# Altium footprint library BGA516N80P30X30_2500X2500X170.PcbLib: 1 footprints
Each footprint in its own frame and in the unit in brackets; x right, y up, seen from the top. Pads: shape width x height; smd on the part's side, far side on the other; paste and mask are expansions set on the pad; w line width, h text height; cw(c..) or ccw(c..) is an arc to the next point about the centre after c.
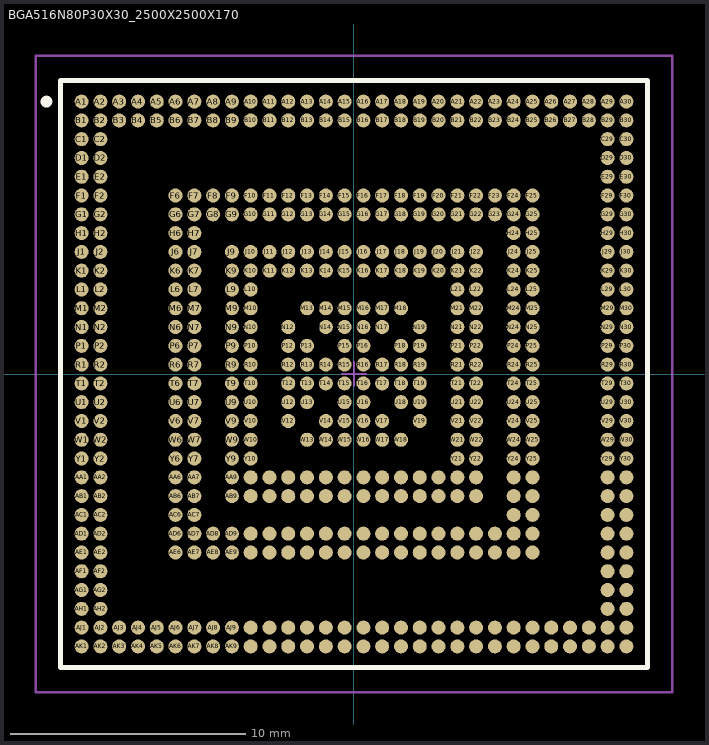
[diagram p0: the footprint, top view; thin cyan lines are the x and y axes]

## BGA516N80P30X30_2500X2500X170 [mm] "BGA,0.80mm pitch,square;516 pin,30 columns X 30 rows,25.00mm X 25.00mm X 1.70mm H"
height 1.7
pads (516):
  round 0.6 smd paste+0 mask+0: A1(-11.6,11.6) A2(-10.8,11.6) A3(-10,11.6) A4(-9.2,11.6) A5(-8.4,11.6) A6(-7.6,11.6) A7(-6.8,11.6) A8(-6,11.6) A9(-5.2,11.6) A10(-4.4,11.6) A11(-3.6,11.6) A12(-2.8,11.6) A13(-2,11.6) A14(-1.2,11.6) A15(-0.4,11.6) A16(0.4,11.6) A17(1.2,11.6) A18(2,11.6) A19(2.8,11.6) A20(3.6,11.6) A21(4.4,11.6) A22(5.2,11.6) A23(6,11.6) A24(6.8,11.6) A25(7.6,11.6) A26(8.4,11.6) A27(9.2,11.6) A28(10,11.6) A29(10.8,11.6) A30(11.6,11.6) AA1(-11.6,-4.4) AA2(-10.8,-4.4) AA6(-7.6,-4.4) AA7(-6.8,-4.4) AA9(-5.2,-4.4) AA10(-4.4,-4.4) AA11(-3.6,-4.4) AA12(-2.8,-4.4) AA13(-2,-4.4) AA14(-1.2,-4.4) AA15(-0.4,-4.4) AA16(0.4,-4.4) AA17(1.2,-4.4) AA18(2,-4.4) AA19(2.8,-4.4) AA20(3.6,-4.4) AA21(4.4,-4.4) AA22(5.2,-4.4) AA24(6.8,-4.4) AA25(7.6,-4.4) AA29(10.8,-4.4) AA30(11.6,-4.4) AB1(-11.6,-5.2) AB2(-10.8,-5.2) AB6(-7.6,-5.2) AB7(-6.8,-5.2) AB9(-5.2,-5.2) AB10(-4.4,-5.2) AB11(-3.6,-5.2) AB12(-2.8,-5.2) AB13(-2,-5.2) AB14(-1.2,-5.2) AB15(-0.4,-5.2) AB16(0.4,-5.2) AB17(1.2,-5.2) AB18(2,-5.2) AB19(2.8,-5.2) AB20(3.6,-5.2) AB21(4.4,-5.2) AB22(5.2,-5.2) AB24(6.8,-5.2) AB25(7.6,-5.2) AB29(10.8,-5.2) AB30(11.6,-5.2) AC1(-11.6,-6) AC2(-10.8,-6) AC6(-7.6,-6) AC7(-6.8,-6) AC24(6.8,-6) AC25(7.6,-6) AC29(10.8,-6) AC30(11.6,-6) AD1(-11.6,-6.8) AD2(-10.8,-6.8) AD6(-7.6,-6.8) AD7(-6.8,-6.8) AD8(-6,-6.8) AD9(-5.2,-6.8) AD10(-4.4,-6.8) AD11(-3.6,-6.8) AD12(-2.8,-6.8) AD13(-2,-6.8) AD14(-1.2,-6.8) AD15(-0.4,-6.8) AD16(0.4,-6.8) AD17(1.2,-6.8) AD18(2,-6.8) AD19(2.8,-6.8) AD20(3.6,-6.8) AD21(4.4,-6.8) AD22(5.2,-6.8) AD23(6,-6.8) AD24(6.8,-6.8) AD25(7.6,-6.8) AD29(10.8,-6.8) AD30(11.6,-6.8) AE1(-11.6,-7.6) AE2(-10.8,-7.6) AE6(-7.6,-7.6) AE7(-6.8,-7.6) AE8(-6,-7.6) AE9(-5.2,-7.6) AE10(-4.4,-7.6) AE11(-3.6,-7.6) AE12(-2.8,-7.6) AE13(-2,-7.6) AE14(-1.2,-7.6) AE15(-0.4,-7.6) AE16(0.4,-7.6) AE17(1.2,-7.6) AE18(2,-7.6) AE19(2.8,-7.6) AE20(3.6,-7.6) AE21(4.4,-7.6) AE22(5.2,-7.6) AE23(6,-7.6) AE24(6.8,-7.6) AE25(7.6,-7.6) AE29(10.8,-7.6) AE30(11.6,-7.6) AF1(-11.6,-8.4) AF2(-10.8,-8.4) AF29(10.8,-8.4) AF30(11.6,-8.4) AG1(-11.6,-9.2) AG2(-10.8,-9.2) AG29(10.8,-9.2) AG30(11.6,-9.2) AH1(-11.6,-10) AH2(-10.8,-10) AH29(10.8,-10) AH30(11.6,-10) AJ1(-11.6,-10.8) AJ2(-10.8,-10.8) AJ3(-10,-10.8) AJ4(-9.2,-10.8) AJ5(-8.4,-10.8) AJ6(-7.6,-10.8) AJ7(-6.8,-10.8) AJ8(-6,-10.8) AJ9(-5.2,-10.8) AJ10(-4.4,-10.8) AJ11(-3.6,-10.8) AJ12(-2.8,-10.8) AJ13(-2,-10.8) AJ14(-1.2,-10.8) AJ15(-0.4,-10.8) AJ16(0.4,-10.8) AJ17(1.2,-10.8) AJ18(2,-10.8) AJ19(2.8,-10.8) AJ20(3.6,-10.8) AJ21(4.4,-10.8) AJ22(5.2,-10.8) AJ23(6,-10.8) AJ24(6.8,-10.8) AJ25(7.6,-10.8) AJ26(8.4,-10.8) AJ27(9.2,-10.8) AJ28(10,-10.8) AJ29(10.8,-10.8) AJ30(11.6,-10.8) AK1(-11.6,-11.6) AK2(-10.8,-11.6) AK3(-10,-11.6) AK4(-9.2,-11.6) AK5(-8.4,-11.6) AK6(-7.6,-11.6) AK7(-6.8,-11.6) AK8(-6,-11.6) AK9(-5.2,-11.6) AK10(-4.4,-11.6) AK11(-3.6,-11.6) AK12(-2.8,-11.6) AK13(-2,-11.6) AK14(-1.2,-11.6) AK15(-0.4,-11.6) AK16(0.4,-11.6) AK17(1.2,-11.6) AK18(2,-11.6) AK19(2.8,-11.6) AK20(3.6,-11.6) AK21(4.4,-11.6) AK22(5.2,-11.6) AK23(6,-11.6) AK24(6.8,-11.6) AK25(7.6,-11.6) AK26(8.4,-11.6) AK27(9.2,-11.6) AK28(10,-11.6) AK29(10.8,-11.6) AK30(11.6,-11.6) B1(-11.6,10.8) B2(-10.8,10.8) B3(-10,10.8) B4(-9.2,10.8) B5(-8.4,10.8) B6(-7.6,10.8) B7(-6.8,10.8) B8(-6,10.8) B9(-5.2,10.8) B10(-4.4,10.8) B11(-3.6,10.8) B12(-2.8,10.8) B13(-2,10.8) B14(-1.2,10.8) B15(-0.4,10.8) B16(0.4,10.8) B17(1.2,10.8) B18(2,10.8) B19(2.8,10.8) B20(3.6,10.8) B21(4.4,10.8) B22(5.2,10.8) B23(6,10.8) B24(6.8,10.8) B25(7.6,10.8) B26(8.4,10.8) B27(9.2,10.8) B28(10,10.8) B29(10.8,10.8) B30(11.6,10.8) C1(-11.6,10) C2(-10.8,10) C29(10.8,10) C30(11.6,10) D1(-11.6,9.2) D2(-10.8,9.2) D29(10.8,9.2) D30(11.6,9.2) E1(-11.6,8.4) E2(-10.8,8.4) E29(10.8,8.4) E30(11.6,8.4) F1(-11.6,7.6) F2(-10.8,7.6) F6(-7.6,7.6) F7(-6.8,7.6) F8(-6,7.6) F9(-5.2,7.6) F10(-4.4,7.6) F11(-3.6,7.6) F12(-2.8,7.6) F13(-2,7.6) F14(-1.2,7.6) F15(-0.4,7.6) F16(0.4,7.6) F17(1.2,7.6) F18(2,7.6) F19(2.8,7.6) F20(3.6,7.6) F21(4.4,7.6) F22(5.2,7.6) F23(6,7.6) F24(6.8,7.6) F25(7.6,7.6) F29(10.8,7.6) F30(11.6,7.6) G1(-11.6,6.8) G2(-10.8,6.8) G6(-7.6,6.8) G7(-6.8,6.8) G8(-6,6.8) G9(-5.2,6.8) G10(-4.4,6.8) G11(-3.6,6.8) G12(-2.8,6.8) G13(-2,6.8) G14(-1.2,6.8) G15(-0.4,6.8) G16(0.4,6.8) G17(1.2,6.8) G18(2,6.8) G19(2.8,6.8) G20(3.6,6.8) G21(4.4,6.8) G22(5.2,6.8) G23(6,6.8) G24(6.8,6.8) G25(7.6,6.8) G29(10.8,6.8) G30(11.6,6.8) H1(-11.6,6) H2(-10.8,6) H6(-7.6,6) H7(-6.8,6) H24(6.8,6) H25(7.6,6) H29(10.8,6) H30(11.6,6) J1(-11.6,5.2) J2(-10.8,5.2) J6(-7.6,5.2) J7(-6.8,5.2) J9(-5.2,5.2) J10(-4.4,5.2) J11(-3.6,5.2) J12(-2.8,5.2) J13(-2,5.2) J14(-1.2,5.2) J15(-0.4,5.2) J16(0.4,5.2) J17(1.2,5.2) J18(2,5.2) J19(2.8,5.2) J20(3.6,5.2) J21(4.4,5.2) J22(5.2,5.2) J24(6.8,5.2) J25(7.6,5.2) J29(10.8,5.2) J30(11.6,5.2) K1(-11.6,4.4) K2(-10.8,4.4) K6(-7.6,4.4) K7(-6.8,4.4) K9(-5.2,4.4) K10(-4.4,4.4) K11(-3.6,4.4) K12(-2.8,4.4) K13(-2,4.4) K14(-1.2,4.4) K15(-0.4,4.4) K16(0.4,4.4) K17(1.2,4.4) K18(2,4.4) K19(2.8,4.4) K20(3.6,4.4) K21(4.4,4.4) K22(5.2,4.4) K24(6.8,4.4) K25(7.6,4.4) K29(10.8,4.4) K30(11.6,4.4) L1(-11.6,3.6) L2(-10.8,3.6) L6(-7.6,3.6) L7(-6.8,3.6) L9(-5.2,3.6) L10(-4.4,3.6) L21(4.4,3.6) L22(5.2,3.6) L24(6.8,3.6) L25(7.6,3.6) L29(10.8,3.6) L30(11.6,3.6) M1(-11.6,2.8) M2(-10.8,2.8) M6(-7.6,2.8) M7(-6.8,2.8) M9(-5.2,2.8) M10(-4.4,2.8) M13(-2,2.8) M14(-1.2,2.8) M15(-0.4,2.8) M16(0.4,2.8) M17(1.2,2.8) M18(2,2.8) M21(4.4,2.8) M22(5.2,2.8) M24(6.8,2.8) M25(7.6,2.8) M29(10.8,2.8) M30(11.6,2.8) N1(-11.6,2) N2(-10.8,2) N6(-7.6,2) N7(-6.8,2) N9(-5.2,2) N10(-4.4,2) N12(-2.8,2) N14(-1.2,2) N15(-0.4,2) N16(0.4,2) N17(1.2,2) N19(2.8,2) N21(4.4,2) N22(5.2,2) N24(6.8,2) N25(7.6,2) N29(10.8,2) N30(11.6,2) P1(-11.6,1.2) P2(-10.8,1.2) P6(-7.6,1.2) P7(-6.8,1.2) P9(-5.2,1.2) P10(-4.4,1.2) P12(-2.8,1.2) P13(-2,1.2) P15(-0.4,1.2) P16(0.4,1.2) P18(2,1.2) P19(2.8,1.2) P21(4.4,1.2) P22(5.2,1.2) P24(6.8,1.2) P25(7.6,1.2) P29(10.8,1.2) P30(11.6,1.2) R1(-11.6,0.4) R2(-10.8,0.4) R6(-7.6,0.4) R7(-6.8,0.4) R9(-5.2,0.4) R10(-4.4,0.4) R12(-2.8,0.4) R13(-2,0.4) R14(-1.2,0.4) R15(-0.4,0.4) R16(0.4,0.4) R17(1.2,0.4) R18(2,0.4) R19(2.8,0.4) R21(4.4,0.4) R22(5.2,0.4) R24(6.8,0.4) R25(7.6,0.4) R29(10.8,0.4) R30(11.6,0.4) T1(-11.6,-0.4) T2(-10.8,-0.4) T6(-7.6,-0.4) T7(-6.8,-0.4) T9(-5.2,-0.4) T10(-4.4,-0.4) T12(-2.8,-0.4) T13(-2,-0.4) T14(-1.2,-0.4) T15(-0.4,-0.4) T16(0.4,-0.4) T17(1.2,-0.4) T18(2,-0.4) T19(2.8,-0.4) T21(4.4,-0.4) T22(5.2,-0.4) T24(6.8,-0.4) T25(7.6,-0.4) T29(10.8,-0.4) T30(11.6,-0.4) U1(-11.6,-1.2) U2(-10.8,-1.2) U6(-7.6,-1.2) U7(-6.8,-1.2) U9(-5.2,-1.2) U10(-4.4,-1.2) U12(-2.8,-1.2) U13(-2,-1.2) U15(-0.4,-1.2) U16(0.4,-1.2) U18(2,-1.2) U19(2.8,-1.2) U21(4.4,-1.2) U22(5.2,-1.2) U24(6.8,-1.2) U25(7.6,-1.2) U29(10.8,-1.2) U30(11.6,-1.2) V1(-11.6,-2) V2(-10.8,-2) V6(-7.6,-2) V7(-6.8,-2) V9(-5.2,-2) V10(-4.4,-2) V12(-2.8,-2) V14(-1.2,-2) V15(-0.4,-2) V16(0.4,-2) V17(1.2,-2) V19(2.8,-2) V21(4.4,-2) V22(5.2,-2) V24(6.8,-2) V25(7.6,-2) V29(10.8,-2) V30(11.6,-2) W1(-11.6,-2.8) W2(-10.8,-2.8) W6(-7.6,-2.8) W7(-6.8,-2.8) W9(-5.2,-2.8) W10(-4.4,-2.8) W13(-2,-2.8) W14(-1.2,-2.8) W15(-0.4,-2.8) W16(0.4,-2.8) W17(1.2,-2.8) W18(2,-2.8) W21(4.4,-2.8) W22(5.2,-2.8) W24(6.8,-2.8) W25(7.6,-2.8) W29(10.8,-2.8) W30(11.6,-2.8) Y1(-11.6,-3.6) Y2(-10.8,-3.6) Y6(-7.6,-3.6) Y7(-6.8,-3.6) Y9(-5.2,-3.6) Y10(-4.4,-3.6) Y21(4.4,-3.6) Y22(5.2,-3.6) Y24(6.8,-3.6) Y25(7.6,-3.6) Y29(10.8,-3.6) Y30(11.6,-3.6)
Top Overlay:
  circle w0.25: c-13.1,11.6 r0.125
  lines w0.2: -12.5,-12.5 12.5,-12.5 12.5,12.5 -12.5,12.5 -12.5,-12.5
M3 (ASY_Text_Top):
  text ".DESIGNATOR" at 0,0 h1.2
M13 (CMP_Body_OTL_Top):
  lines w0.1: -12.5,-12.5 12.5,-12.5 12.5,12.5 -12.5,12.5 -12.5,-12.5
M15 (CMP_Courtyard_Top):
  lines w0.1: -0.5,0 0.5,0 ; 0,-0.5 0,0.5 ; -13.55,-13.55 13.55,-13.55 13.55,13.55 -13.55,13.55 -13.55,-13.55
3D body "LFBGA-516-1.stp": height 1.71, standoff 0, extent -12.5,-12.5 12.5,12.5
